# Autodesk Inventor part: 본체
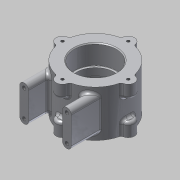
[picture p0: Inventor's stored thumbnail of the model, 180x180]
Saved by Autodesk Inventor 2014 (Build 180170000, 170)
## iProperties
Created: 2015-03
Part Number: 본체
Material: 알루미늄 6061
Document SubType Name: Modeling
Designer: MYHOME
Mass: 450.776 g
Surface Area: 332.745 cm^2
Volume: 166.338 cm^3
Density: 2.71 g/cm^3
Appearance: 알루미늄 - 평지
Author: MYHOME
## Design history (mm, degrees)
sketch "스케치1"
  geometry: C1 r 37 at (0, 0); 1 further point
  constraints: 1 centre point, 1 coincident
  dimensions: "d0" = 74 diameter of C1
extrude "돌출1" new body sketch "스케치1" stored distance "d1" = 52; taper "d2" = 0 deg
sketch "스케치2"
  geometry: C1 r 7 at (0, 37); 1 further point
  constraints: 2 vertical alignment, 1 centre point, 1 other
  dimensions: "d3" = 7 radius of C1
extrude "돌출2" join sketch "스케치2" distance "d4" = 15; taper "d5" = 0 deg
hole "구멍1" diameter "d11" = 42; stored, may be unused: countersink angle "d15" = 90 deg, drill point angle "d17" = 0 deg; dims "d9" = 10, "d10" = 10, "d12" = 6, "d13" = 47, "d14" = 22, "d16" = 26
sketch "스케치3"
  geometry: L1 (-29, -22.978)-(-19, -22.978); L2 (-19, -22.978)-(-19, -56); L3 (-19, -56)-(-29, -56); L4 (-29, -56)-(-29, -22.978); L5 (-29, -22.978)-(-19, -56); L6 (-19, -22.978)-(-29, -56); L7 (19, -22.978)-(29, -22.978); L8 (29, -22.978)-(29, -56); L9 (29, -56)-(19, -56); L10 (19, -56)-(19, -22.978); L11 (19, -22.978)-(29, -56); L12 (29, -22.978)-(19, -56); A1 r 37 centre (0, 0) between (-36.338, -6.969) and (-6.969, -36.338) reference; A2 r 37 centre (0, 0) between (6.969, -36.338) and (36.338, -6.969) reference; 3 further points
  constraints: 24 end point, 4 midpoint, 4 parallel, 2 horizontal, 2 perpendicular, 2 point on circle, 1 collinear
  dimensions: "d18" = 48 distance of point (24, -39.489) point (-24, -39.489); "d19" = 24 horizontal distance of point (-24, -39.489) point (0, 0); "d20" = 56 distance from line of L3 point (0, 0); "d21" = 10 distance of L1.start L1.end; "d22" = 10 distance of L7.start L7.end
extrude "돌출3" join sketch "스케치3" stored distance "d23" = 40; taper "d24" = 0 deg
sketch "스케치4"
  geometry: A1 r 7 centre (0, 37) between (6.969, 36.338) and (-6.969, 36.338) reference; A2 r 7 centre (-37, 0) between (-36.338, 6.969) and (-36.338, -6.969) reference; A3 r 7 centre (0, -37) between (-6.969, -36.338) and (6.969, -36.338) reference; A4 r 7 centre (37, 0) between (36.338, -6.969) and (36.338, 6.969) reference; 4 further points
  constraints: 4 coincident
hole "구멍2" sketch "스케치4" at (0, 37), (-37, 0), (0, -37), (37, 0) diameter "d25" = 3.242; stored, may be unused: countersink angle "d29" = 90 deg, drill point angle "d31" = 118 deg; dims "d26" = 8, "d27" = 47, "d28" = 22, "d30" = 11
chamfer "모따기1" distance "d32" = 1; stored, may be unused: second distance "d33" = 2, angle "d34" = 45 deg
fillet "모깎기1" dims "d35" = 3
fillet "모깎기2" dims "d36" = 0.3
fillet "모깎기3" dims "d37" = 5
fillet "모깎기4" dims "d38" = 3
fillet "모깎기5" dims "d39" = 3
sketch "스케치5"
  geometry: L1 (43, 30)-(43, 0) reference; L2 (53, 30)-(53, 0) reference; A1 r 5 centre (0, 0) between (-5, 0) and (5, 0) reference; A2 r 5 centre (0, 30) between (5, 30) and (-5, 30) reference; A3 r 5 centre (48, 30) between (53, 30) and (43, 30) reference; A4 r 5 centre (48, 0) between (43, 0) and (53, 0) reference; 5 further points
  constraints: 4 coincident
hole "구멍3" sketch "스케치5" at (0, 30), (0, 0), (48, 0), (48, 30) diameter "d40" = 4.134; stored, may be unused: countersink angle "d44" = 90 deg, drill point angle "d46" = 118 deg; dims "d41" = 6, "d42" = 47, "d43" = 22, "d45" = 8
sketch "스케치6"
  geometry: L1 (0, 0)-(-44, 0); L2 (0, 0)-(-26.163, 26.163); A1 r 37 centre (0, 0) between (-9.104, 35.863) and (-35.863, 9.104) reference; A2 r 7 centre (-37, 0) between (-38.239, 6.889) and (-38.239, -6.889) reference; 2 further points
  constraints: 4 end point, 2 point on circle, 1 coincident
  dimensions: "d47" = 45 deg angle of L1 L2
node "작업 평면3"
  node "작업 평면2"
sketch "스케치8"
  geometry: 2 further points
  constraints: 1 coincident, 1 other
extrude "돌출4" join sketch "스케치8" stored distance "d51" = 40; taper "d52" = 0 deg
node "솔리드1"
pattern_circular "원형 패턴1" dims angle "d7" = 360 deg
mirror "대칭1"
mirror "대칭2"
mirror "대칭3"
node "투영된 루프1"
other parameters: "d50" = 0.5
